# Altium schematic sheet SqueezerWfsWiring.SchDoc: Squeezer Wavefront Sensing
size B; Organization: LIGO Laboratory; Address1: California Institute of Technology; Address2: Massachusetts Institute of Technology; SheetNumber: 28; SheetTotal: 37; DrawnBy: R.  Abbott; Engineer: R.  Abbott; PageSetup: Record=PageOptions¦CenterHorizontal=True¦CenterVertical=True¦PrintScale=1.09¦XCorrection=1.00¦YCorrection=1.00¦PrintKind=0¦BorderSize=5000000¦LeftOffset=0¦BottomOffset=0¦Orientation=2¦PaperLength=1000¦PaperWidth=1000¦Scale=100¦PaperSource=7¦PrintQuality=-4¦MediaType=1¦DitherType=10¦PaperKind=11x17¦PrintScaleMode=1
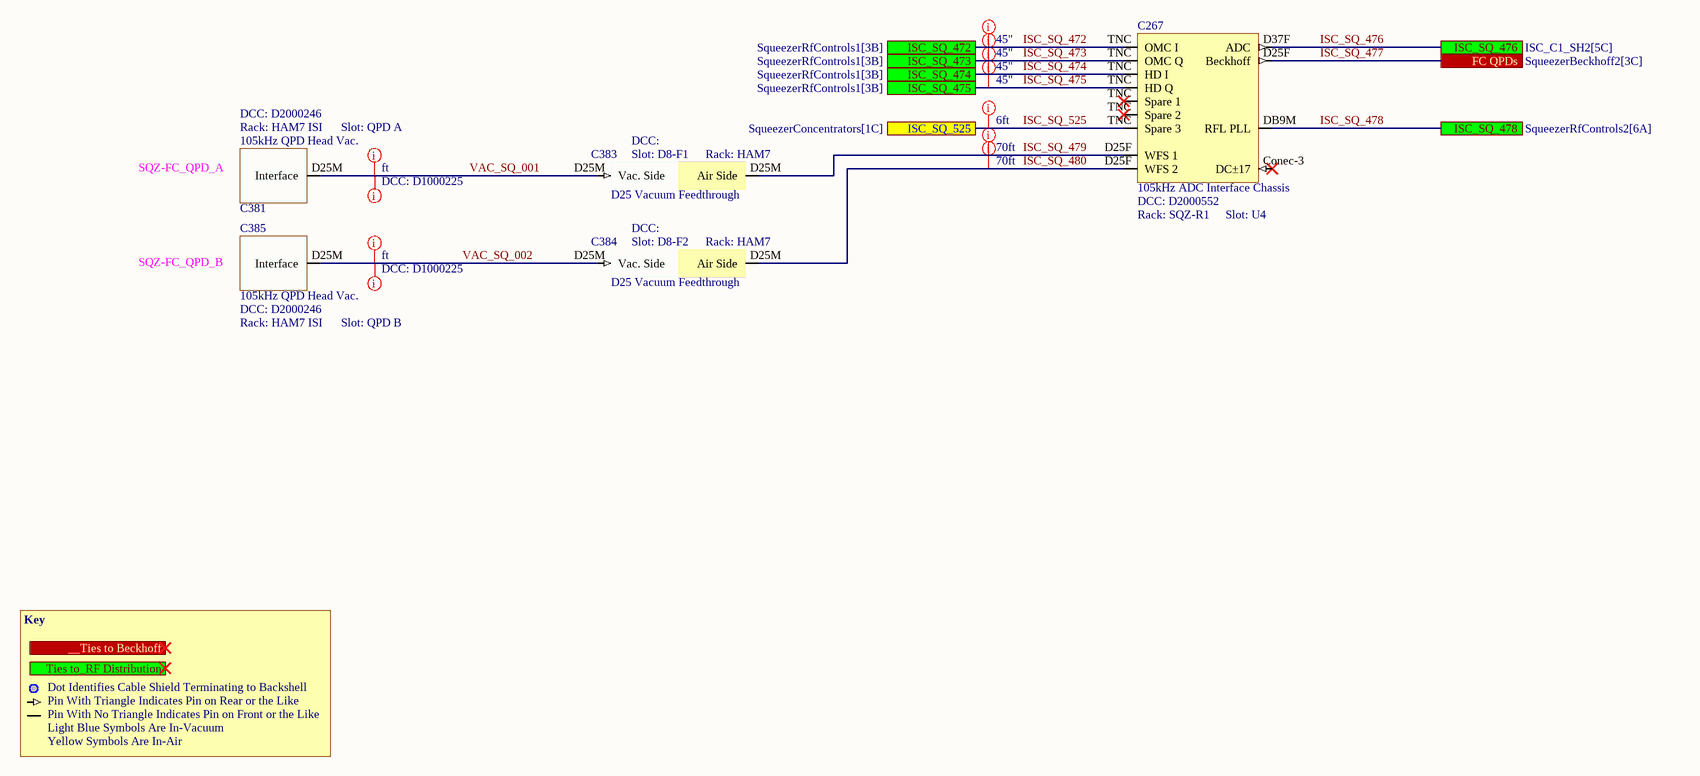
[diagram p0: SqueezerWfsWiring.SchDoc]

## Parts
C267  105kHz ADC Interface Chassis  DCC: D2000552  Rack: SQZ-R1  Slot: U4
C381  105kHz QPD Head Vac.  DCC: D2000246  Rack: HAM7 ISI  Slot: QPD A
C383  D25 Vacuum Feedthrough  Rack: HAM7  Slot: D8-F1
C384  D25 Vacuum Feedthrough  Rack: HAM7  Slot: D8-F2
C385  105kHz QPD Head Vac.  DCC: D2000246  Rack: HAM7 ISI  Slot: QPD B

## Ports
__Ties to Beckhoff, FC QPDs (see SqueezerBeckhoff2[3C]), ISC_SQ_472 (see SqueezerRfControls1[3B]), ISC_SQ_473 (see SqueezerRfControls1[3B]), ISC_SQ_474 (see SqueezerRfControls1[3B]), ISC_SQ_475 (see SqueezerRfControls1[3B]), ISC_SQ_476 (see ISC_C1_SH2[5C]), ISC_SQ_478 (see SqueezerRfControls2[6A]), ISC_SQ_525 (see SqueezerConcentrators[1C]), Ties to_RF Distribution

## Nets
ISC_SQ_472: C267.TNC(OMC_I) ; port ISC_SQ_472
ISC_SQ_473: C267.TNC(OMC_Q) ; port ISC_SQ_473
ISC_SQ_474: C267.TNC(HD_I) ; port ISC_SQ_474
ISC_SQ_475: C267.TNC(HD_Q) ; port ISC_SQ_475
ISC_SQ_476: C267.D37F(ADC) ; port ISC_SQ_476
ISC_SQ_477: C267.D25F(Beckhoff) ; port FC QPDs
ISC_SQ_478: C267.DB9M(RFL_PLL) ; port ISC_SQ_478
ISC_SQ_479: C267.D25F(WFS_1) C383.D25M(Air_Side)
ISC_SQ_480: C267.D25F(WFS_2) C384.D25M(Air_Side)
ISC_SQ_525: C267.TNC(Spare_3) ; port ISC_SQ_525
VAC_SQ_001: C381.D25M(Interface) C383.D25M(Vac._Side)
VAC_SQ_002: C384.D25M(Vac._Side) C385.D25M(Interface)

Not connected (* = marked no-connect by the designer): C267 Conec-3(DC±17)*

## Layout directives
Length: 70ft: ISC_SQ_479, ISC_SQ_480
DCC: D1000225: VAC_SQ_001, VAC_SQ_002
Length: ft: VAC_SQ_001, VAC_SQ_002
Length: 45": ISC_SQ_472, ISC_SQ_473, ISC_SQ_474, ISC_SQ_475
Length: 6ft: ISC_SQ_525

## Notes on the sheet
- SQZ-FC_QPD_A
- SQZ-FC_QPD_B
- Key
- Dot Identifies Cable Shield Terminating to Backshell
- Pin With Triangle Indicates Pin on Rear or the Like
- Pin With No Triangle Indicates Pin on Front or the Like
- Light Blue Symbols Are In-Vacuum
- Yellow Symbols Are In-Air

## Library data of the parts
C267 = 105kHz ADC Interface Chassis: Serial: Sxxxxxxx; System: ISC
C381 C385 = 105kHz QPD Head Vac.: Serial: Sxxxxxxx; System: ISC
C383 C384 = VacFeedD25: Serial: Sxxxxxxx; System: ISC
